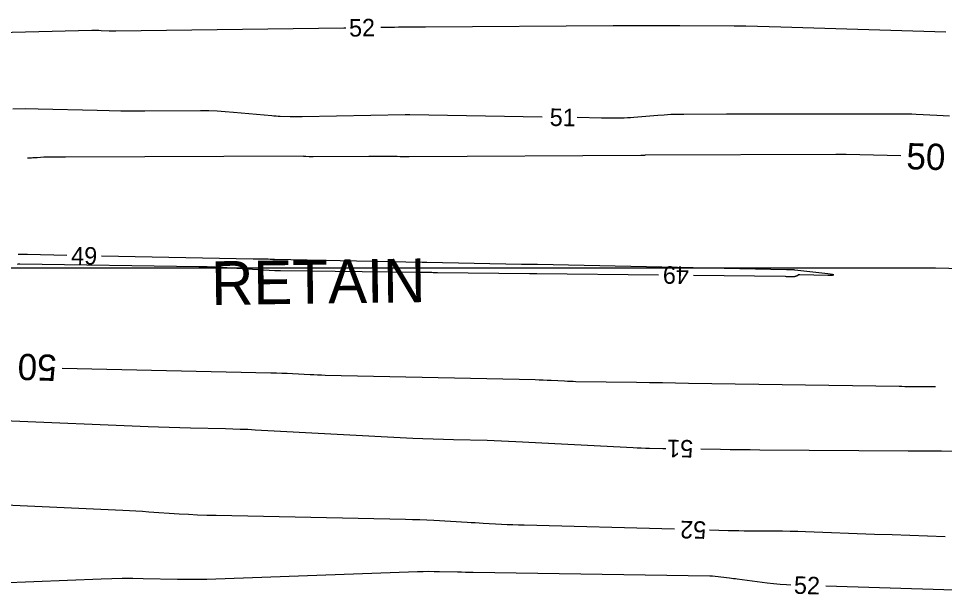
# Model space of a CAD drawing. Extents: x 2384780 to 2405861, y 547869 to 573706.
# Drawn here: x 2391697.7 to 2391803.7, y 552624.6 to 552690.5 of the extents above; entities that cross this region are included whole.
import ezdxf

# ---------------------------------------------------------------- set-up
doc = ezdxf.new("R2010")
doc.units = 0
for name, color, linetype in [('Old_Level_5', 7, 'Continuous'), ('Old_Level_60', 7, 'Continuous'), ('Old_Level_61', 7, 'Continuous')]:
    doc.layers.add(name, color=color, linetype=linetype)

msp = doc.modelspace()

# ---------------------------------------------------------------- linework, layer by layer
at = {"layer": 'Old_Level_5'}
msp.add_lwpolyline([(2391368.144, 552652.22025), (2391566.47975, 552661.99175), (2391802.65175, 552661.99175), (2391851.9615, 552660.77025)], dxfattribs=at)
at = {"layer": 'Old_Level_60'}
for points in [[(2391680.24, 552688.533), (2391706.08725, 552689.1635), (2391706.35875, 552689.16775), (2391706.63025, 552689.167), (2391706.90175, 552689.1615), (2391707.17325, 552689.151), (2391708.0595, 552689.1085), (2391708.2495, 552689.101), (2391708.4395, 552689.096), (2391708.62975, 552689.09425), (2391708.81975, 552689.09525), (2391734.92525, 552689.4225), (2391735.1585, 552689.42575)], [(2391739.15775, 552689.498), (2391739.85575, 552689.51225), (2391740.297, 552689.52075), (2391740.73825, 552689.528), (2391741.1795, 552689.5345), (2391741.62075, 552689.53975), (2391743.062, 552689.5555), (2391743.371, 552689.5585), (2391743.67975, 552689.56125), (2391743.98875, 552689.56375), (2391744.2975, 552689.5655), (2391765.78175, 552689.68725), (2391767.68775, 552689.6955), (2391769.5935, 552689.699), (2391771.4995, 552689.69775), (2391773.4055, 552689.69175), (2391779.6315, 552689.6635), (2391780.9655, 552689.653), (2391782.2995, 552689.6335), (2391783.63325, 552689.605), (2391784.96675, 552689.5675), (2391803.8365, 552688.97225)], [(2391757.636, 552679.2305), (2391742.48675, 552679.4825), (2391742.43425, 552679.48325), (2391742.38175, 552679.48375), (2391742.32925, 552679.484), (2391742.277, 552679.48425), (2391742.1055, 552679.48425), (2391742.069, 552679.484), (2391742.03225, 552679.48375), (2391741.9955, 552679.4835), (2391741.95875, 552679.48275), (2391730.14825, 552679.2585), (2391729.80575, 552679.254), (2391729.463, 552679.25325), (2391729.1205, 552679.2565), (2391728.778, 552679.26375), (2391727.65875, 552679.2935), (2391727.41925, 552679.302), (2391727.17975, 552679.31425), (2391726.9405, 552679.33075), (2391726.7015, 552679.351), (2391722.30575, 552679.76225), (2391721.3635, 552679.83875), (2391720.42, 552679.8925), (2391719.4755, 552679.923), (2391718.53, 552679.9305), (2391712.15775, 552679.90375), (2391710.79225, 552679.90325), (2391709.427, 552679.913), (2391708.06175, 552679.93325), (2391706.69675, 552679.964), (2391699.9445, 552680.14125), (2391698.49825, 552680.1595), (2391697.053, 552680.1385)], [(2391804.27575, 552679.33575), (2391803.549, 552679.36125), (2391802.8225, 552679.3945), (2391800.4495, 552679.517), (2391799.941, 552679.54), (2391799.43225, 552679.55625), (2391798.92325, 552679.56625), (2391798.41425, 552679.5695), (2391784.228, 552679.57225), (2391782.859, 552679.57175), (2391781.49, 552679.5695), (2391780.12075, 552679.566), (2391778.75175, 552679.56075), (2391773.8595, 552679.53925), (2391773.1115, 552679.5285), (2391772.36425, 552679.5025), (2391771.6175, 552679.46175), (2391770.8715, 552679.4055), (2391768.12175, 552679.171), (2391767.75675, 552679.14375), (2391767.39125, 552679.12425), (2391767.0255, 552679.11275), (2391766.6595, 552679.10875), (2391765.46325, 552679.10875), (2391765.207, 552679.10925), (2391764.95075, 552679.11075), (2391764.69425, 552679.1135), (2391764.438, 552679.11725), (2391761.6355, 552679.16375)], [(2391703.20925, 552663.402), (2391698.7395, 552663.4935), (2391697.65775, 552663.5155)], [(2391774.9595, 552661.1225), (2391785.43725, 552661.00275), (2391785.5795, 552661.00125), (2391785.722, 552661.0005), (2391785.86425, 552661), (2391786.00675, 552661), (2391786.543, 552661.00125), (2391786.60575, 552661.00575), (2391786.666, 552661.01875), (2391786.7235, 552661.04025), (2391786.77875, 552661.07025), (2391786.955, 552661.18275), (2391786.9935, 552661.2035), (2391787.03375, 552661.21825), (2391787.076, 552661.2265), (2391787.11975, 552661.2285), (2391790.33675, 552661.14375), (2391790.85425, 552661.138), (2391791.0285, 552661.157), (2391790.859, 552661.201), (2391790.34575, 552661.2695), (2391786.5695, 552661.71675), (2391786.4735, 552661.72675), (2391786.37725, 552661.734), (2391786.28075, 552661.7385), (2391786.18425, 552661.7405), (2391785.86875, 552661.742), (2391785.801, 552661.7425), (2391785.73325, 552661.74325), (2391785.66575, 552661.74425), (2391785.598, 552661.7455), (2391757.0875, 552662.3395), (2391756.9085, 552662.343), (2391756.7295, 552662.3455), (2391756.5505, 552662.3475), (2391756.3715, 552662.34875), (2391755.787, 552662.35125), (2391755.66175, 552662.352), (2391755.5365, 552662.35325), (2391755.41125, 552662.35525), (2391755.286, 552662.3575), (2391744.43325, 552662.58175), (2391744.38125, 552662.58275), (2391744.329, 552662.5835), (2391744.27675, 552662.58425), (2391744.2245, 552662.58475), (2391744.054, 552662.586), (2391744.0175, 552662.58625), (2391743.981, 552662.58675), (2391743.9445, 552662.58725), (2391743.90775, 552662.588), (2391726.9835, 552662.937), (2391726.742, 552662.9415), (2391726.50025, 552662.94525), (2391726.2585, 552662.94825), (2391726.017, 552662.95025), (2391725.2275, 552662.956), (2391725.05825, 552662.95725), (2391724.88925, 552662.9595), (2391724.72, 552662.962), (2391724.55075, 552662.96525), (2391707.20825, 552663.32025)], [(2391697.58675, 552662.401), (2391697.7125, 552662.414), (2391697.83975, 552662.41725), (2391718.35325, 552662.132), (2391719.2815, 552662.11275), (2391720.20925, 552662.08125), (2391721.1365, 552662.0375), (2391722.063, 552661.98125), (2391725.0895, 552661.77725), (2391725.73825, 552661.738), (2391726.38725, 552661.708), (2391727.03675, 552661.687), (2391727.6865, 552661.67475), (2391743.28975, 552661.49525), (2391743.524, 552661.492), (2391743.7585, 552661.48825), (2391743.99275, 552661.48375), (2391744.227, 552661.4785), (2391744.9925, 552661.45975), (2391745.1565, 552661.456), (2391745.32075, 552661.453), (2391745.48475, 552661.45025), (2391745.64875, 552661.448), (2391756.1845, 552661.3285), (2391756.268, 552661.32775), (2391756.3515, 552661.32725), (2391756.435, 552661.327), (2391756.5185, 552661.32725), (2391756.79125, 552661.32825), (2391756.8495, 552661.3285), (2391756.908, 552661.32825), (2391756.9665, 552661.328), (2391757.02475, 552661.3275), (2391770.95975, 552661.16825)], [(2391696.007, 552644.486), (2391712.518, 552643.81775), (2391713.73625, 552643.77125), (2391714.9545, 552643.7305), (2391716.173, 552643.6955), (2391717.39175, 552643.666), (2391721.37325, 552643.5795), (2391722.22625, 552643.55775), (2391723.079, 552643.52925), (2391723.9315, 552643.49425), (2391724.78375, 552643.4525), (2391742.818, 552642.49975), (2391743.98825, 552642.4425), (2391745.159, 552642.39425), (2391746.33, 552642.355), (2391747.5015, 552642.32475), (2391751.3285, 552642.24075), (2391752.14825, 552642.21975), (2391752.968, 552642.192), (2391753.7875, 552642.158), (2391754.60675, 552642.11775), (2391768.0525, 552641.4025), (2391768.51975, 552641.37975), (2391768.98725, 552641.3615), (2391769.45475, 552641.34775), (2391769.9225, 552641.3385), (2391771.4505, 552641.315), (2391771.778, 552641.31), (2391771.7915, 552641.31)], [(2391775.791, 552641.24875), (2391778.0385, 552641.2145), (2391779.1695, 552641.19825), (2391780.30075, 552641.1845), (2391781.43175, 552641.173), (2391782.563, 552641.16375), (2391799.54475, 552641.04175), (2391800.80875, 552641.03275), (2391802.073, 552641.0235), (2391803.337, 552641.0145), (2391804.601, 552641.0055)], [(2391772.78575, 552632.0505), (2391755.592, 552632.50975), (2391754.941, 552632.52975), (2391754.29025, 552632.55425), (2391753.63975, 552632.5835), (2391752.9895, 552632.6175), (2391750.8655, 552632.73625), (2391750.41025, 552632.76175), (2391749.95525, 552632.78725), (2391749.5, 552632.81275), (2391749.045, 552632.83825), (2391745.24525, 552633.051), (2391744.431, 552633.093), (2391743.61625, 552633.12775), (2391742.80125, 552633.15525), (2391741.98625, 552633.1755), (2391720.31675, 552633.61925), (2391719.25575, 552633.64675), (2391718.19525, 552633.6865), (2391717.13525, 552633.738), (2391716.07575, 552633.80175), (2391712.61575, 552634.02875), (2391711.87425, 552634.07575), (2391711.1325, 552634.11925), (2391710.3905, 552634.159), (2391709.6485, 552634.1955), (2391688.61625, 552635.17725)], [(2391803.74975, 552631.1815), (2391801.72975, 552631.2565), (2391799.70975, 552631.33075), (2391797.68975, 552631.40425), (2391795.66975, 552631.47675), (2391787.78675, 552631.75825), (2391786.90575, 552631.7865), (2391786.02475, 552631.808), (2391785.14375, 552631.82275), (2391784.2625, 552631.831), (2391781.3835, 552631.84675), (2391780.7665, 552631.852), (2391780.14975, 552631.86025), (2391779.53275, 552631.87175), (2391778.916, 552631.8865), (2391776.78425, 552631.9435)], [(2391687.84025, 552625.6285), (2391707.17575, 552626.39825), (2391708.37375, 552626.4365), (2391709.572, 552626.45575), (2391710.77025, 552626.45625), (2391711.96875, 552626.4375), (2391715.88375, 552626.346), (2391716.72275, 552626.3325), (2391717.5615, 552626.33125), (2391718.4005, 552626.3425), (2391719.239, 552626.366), (2391743.36725, 552627.2185), (2391743.999, 552627.236), (2391744.63075, 552627.2445), (2391745.2625, 552627.24325), (2391745.89425, 552627.233), (2391747.9585, 552627.18375), (2391748.40075, 552627.1735), (2391748.843, 552627.16425), (2391749.2855, 552627.156), (2391749.72775, 552627.1485), (2391776.83025, 552626.7215), (2391777.144, 552626.712), (2391777.45725, 552626.6935), (2391777.76975, 552626.66575), (2391778.08175, 552626.629), (2391779.0995, 552626.4945), (2391779.3175, 552626.4655), (2391779.5355, 552626.43675), (2391779.75375, 552626.408), (2391779.97175, 552626.379), (2391783.398, 552625.92575), (2391784.133, 552625.838), (2391784.8695, 552625.76875), (2391785.6075, 552625.71825), (2391786.09575, 552625.69725)], [(2391790.09375, 552625.57225), (2391810.96875, 552624.93625)]]:
    msp.add_lwpolyline(points, dxfattribs=at)
at = {"layer": 'Old_Level_61'}
for points in [[(2391798.698, 552674.77625), (2391792.446, 552674.9325), (2391792.414, 552674.9335), (2391792.382, 552674.9345), (2391792.35, 552674.936), (2391792.318, 552674.9375), (2391792.2135, 552674.943), (2391792.19125, 552674.944), (2391792.16875, 552674.9445), (2391792.14625, 552674.945), (2391792.124, 552674.94525), (2391791.6635, 552674.94525), (2391791.56475, 552674.94525), (2391791.46625, 552674.945), (2391791.3675, 552674.94475), (2391791.269, 552674.9445), (2391769.473, 552674.849), (2391769.4205, 552674.84825), (2391769.36825, 552674.8465), (2391769.316, 552674.84375), (2391769.26375, 552674.83975), (2391769.09325, 552674.82525), (2391769.05675, 552674.8225), (2391769.02, 552674.8205), (2391768.9835, 552674.81925), (2391768.94675, 552674.8185), (2391742.4095, 552674.6905), (2391742.06875, 552674.68975), (2391741.728, 552674.69075), (2391741.387, 552674.69375), (2391741.04625, 552674.6985), (2391739.46525, 552674.72475), (2391739.46075, 552674.725), (2391739.45625, 552674.725), (2391739.4515, 552674.725), (2391739.447, 552674.725), (2391739.432, 552674.725), (2391739.42875, 552674.725), (2391739.42575, 552674.725), (2391739.4225, 552674.725), (2391739.41925, 552674.725), (2391738.5515, 552674.7085), (2391738.3655, 552674.70525), (2391738.17975, 552674.7025), (2391737.99375, 552674.70075), (2391737.80775, 552674.6995), (2391731.414, 552674.666), (2391731.30125, 552674.66675), (2391731.18875, 552674.67025), (2391731.07625, 552674.67675), (2391730.964, 552674.68575), (2391730.597, 552674.72), (2391730.5185, 552674.7265), (2391730.43975, 552674.731), (2391730.361, 552674.7335), (2391730.282, 552674.734), (2391703.057, 552674.61975), (2391702.81075, 552674.61975), (2391702.5645, 552674.6215), (2391702.3185, 552674.625), (2391702.07225, 552674.6305), (2391701.26825, 552674.65175), (2391701.09625, 552674.654), (2391700.924, 552674.6515), (2391700.752, 552674.64425), (2391700.58025, 552674.63225), (2391699.82325, 552674.56975), (2391699.661, 552674.55775), (2391699.49875, 552674.549), (2391699.33625, 552674.5435), (2391699.1735, 552674.54125), (2391698.7095, 552674.539)], [(2391702.70175, 552650.48975), (2391726.59125, 552649.9705), (2391727.20825, 552649.95475), (2391727.82475, 552649.93425), (2391728.44125, 552649.90875), (2391729.05775, 552649.87875), (2391731.07075, 552649.77225), (2391731.50225, 552649.75125), (2391731.93375, 552649.7335), (2391732.3655, 552649.719), (2391732.79725, 552649.70775), (2391756.828, 552649.1805), (2391757.29275, 552649.1685), (2391757.75725, 552649.153), (2391758.22175, 552649.13375), (2391758.686, 552649.11075), (2391760.20275, 552649.03), (2391760.52775, 552649.0145), (2391760.85275, 552649.00175), (2391761.17825, 552648.992), (2391761.5035, 552648.9855), (2391768.4375, 552648.87975), (2391769.9235, 552648.857), (2391771.40925, 552648.83425), (2391772.89525, 552648.8115), (2391774.381, 552648.789), (2391798.49875, 552648.4205), (2391798.82525, 552648.416), (2391799.15175, 552648.412), (2391799.4785, 552648.4085), (2391799.80525, 552648.406), (2391801.0765, 552648.39675), (2391801.203, 552648.39575), (2391801.3295, 552648.395), (2391801.456, 552648.394), (2391801.58225, 552648.39325), (2391801.99525, 552648.39025), (2391802.08375, 552648.3895), (2391802.17225, 552648.3885), (2391802.26075, 552648.3875), (2391802.34925, 552648.386), (2391802.6755, 552648.381)]]:
    msp.add_lwpolyline(points, dxfattribs=at)

# ---------------------------------------------------------------- texts
at = {"layer": 'Old_Level_5'}
msp.add_text('RETAIN', height=5, rotation=0.7926111, dxfattribs=at).set_placement((2391719.78475, 552657.71625))
at = {"layer": 'Old_Level_60'}
for s, rotation, p in [('52', 1.0365083, (2391735.54675, 552688.4285)), ('51', 359.0469806, (2391758.4855, 552678.216)), ('49', 358.8275056, (2391703.7085, 552662.3915)), ('49', 179.3452111, (2391774.45125, 552662.12825)), ('51', 179.1249861, (2391774.94, 552642.262)), ('52', 178.4693333, (2391776.44075, 552632.953)), ('52', 358.20945, (2391786.4345, 552624.6845))]:
    msp.add_text(s, height=2, rotation=rotation, dxfattribs=at).set_placement(p)
at = {"layer": 'Old_Level_61'}
for rotation, p in [(358.5667611, (2391799.29825, 552673.26075)), (178.1186667, (2391702.1135, 552652.01575))]:
    msp.add_text('50', height=3, rotation=rotation, dxfattribs=at).set_placement(p)

doc.saveas('drawing.dxf')
